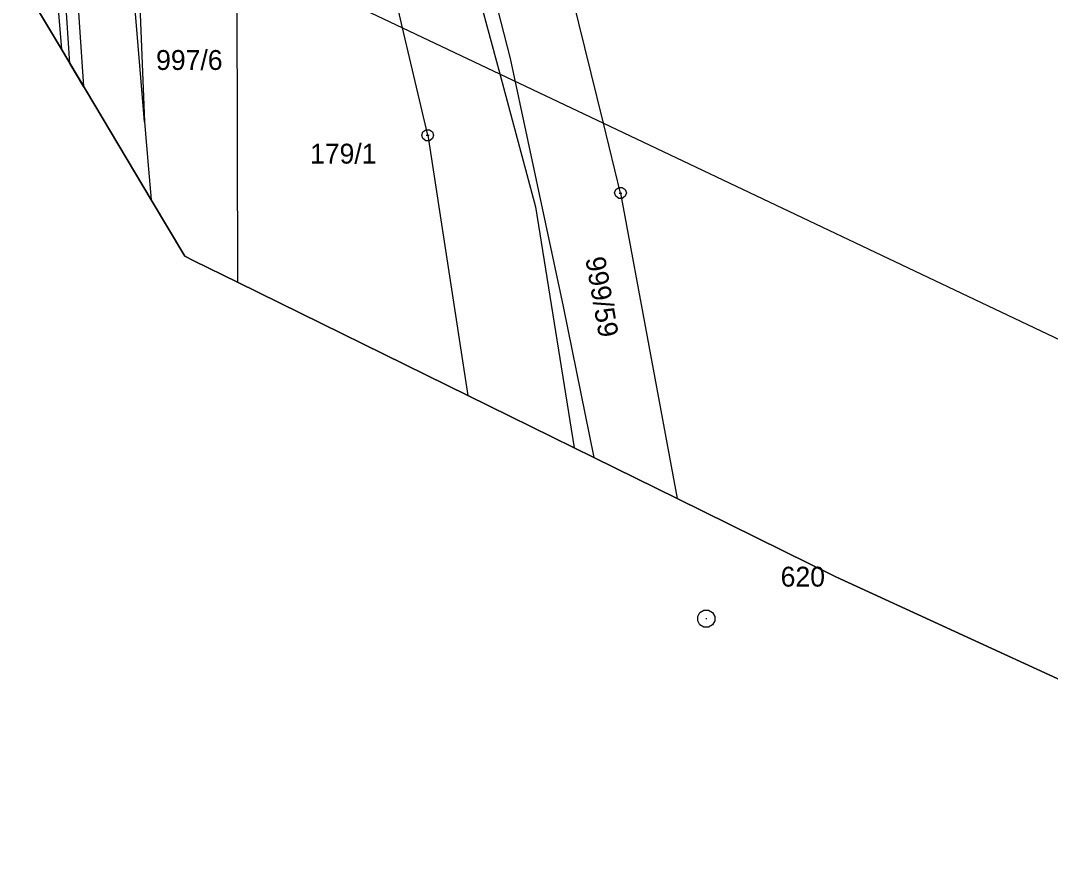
# Model space of a CAD drawing. Extents: x -755359 to -754474, y -1162585 to -1161655.
# Drawn here: x -755133.8 to -755045.7, y -1162567.4 to -1162495.1 of the extents above; entities that cross this region are included whole.
import ezdxf

# ---------------------------------------------------------------- set-up
doc = ezdxf.new("R2010")
doc.units = 0
for name, color, linetype in [('Vrstva 1', 7, 'Continuous'), ('Vrstva 11', 7, 'Continuous'), ('Vrstva 13', 7, 'Continuous'), ('Vrstva 2', 7, 'Continuous'), ('Vrstva 4', 7, 'Continuous'), ('Vrstva 6', 7, 'Continuous'), ('Vrstva 8', 7, 'Continuous')]:
    doc.layers.add(name, color=color, linetype=linetype)

msp = doc.modelspace()

# ---------------------------------------------------------------- linework, layer by layer
at = {"layer": 'Vrstva 1'}
for p, q in [((-755101.11, -1162495.7), (-755105.74, -1162475.9)), ((-755083.94, -1162503.85), (-755090.44, -1162477.46)), ((-755123.93, -1162484.86), (-755123.19, -1162503.76)), ((-755115.28, -1162488.97), (-755101.11, -1162495.7)), ((-755115.28, -1162488.97), (-755115.23, -1162517.45)), ((-755133.78, -1162491.69), (-755130.29, -1162497.54)), ((-755101.11, -1162495.7), (-755083.94, -1162503.85)), ((-755098.96, -1162504.9), (-755101.11, -1162495.7)), ((-755130.29, -1162497.54), (-755122.61, -1162510.43)), ((-755123.19, -1162503.76), (-755122.83, -1162507.8)), ((-755083.94, -1162503.85), (-754997.93, -1162544.71)), ((-755082.47, -1162509.84), (-755083.94, -1162503.85)), ((-755098.96, -1162504.9), (-755095.54, -1162527.15)), ((-755122.83, -1162507.8), (-755122.61, -1162510.43)), ((-755082.47, -1162509.84), (-755077.64, -1162535.97)), ((-755122.61, -1162510.43), (-755119.74, -1162515.24)), ((-755119.74, -1162515.24), (-755118.95, -1162515.63)), ((-755118.95, -1162515.63), (-755115.23, -1162517.45)), ((-755115.23, -1162517.45), (-755095.54, -1162527.15)), ((-755095.54, -1162527.15), (-755084.75, -1162532.46)), ((-755084.75, -1162532.46), (-755077.64, -1162535.97)), ((-755077.64, -1162535.97), (-755064.06, -1162542.65)), ((-755064.06, -1162542.65), (-755010.16, -1162567.43))]:
    msp.add_line(p, q, dxfattribs=at)
at = {"layer": 'Vrstva 11'}
for p, q in [((-755100.87, -1162469.57), (-755092.8, -1162499.65)), ((-755130.29, -1162497.54), (-755133.78, -1162491.69)), ((-755122.61, -1162510.43), (-755130.29, -1162497.54)), ((-755092.8, -1162499.65), (-755089.74, -1162511.02)), ((-755119.74, -1162515.24), (-755122.61, -1162510.43)), ((-755089.74, -1162511.02), (-755086.44, -1162531.63)), ((-755118.95, -1162515.63), (-755119.74, -1162515.24)), ((-755115.23, -1162517.45), (-755118.95, -1162515.63)), ((-755095.54, -1162527.15), (-755115.23, -1162517.45)), ((-755086.44, -1162531.63), (-755095.54, -1162527.15)), ((-755084.75, -1162532.46), (-755086.44, -1162531.63)), ((-755077.64, -1162535.97), (-755084.75, -1162532.46)), ((-755064.06, -1162542.65), (-755077.64, -1162535.97)), ((-755010.16, -1162567.43), (-755064.06, -1162542.65))]:
    msp.add_line(p, q, dxfattribs=at)
at = {"layer": 'Vrstva 13'}
for p, q in [((-755129.57, -1162498.75), (-755130.4, -1162485.92)), ((-755129.4, -1162485.84), (-755128.4, -1162500.72)), ((-755128.4, -1162500.72), (-755129.57, -1162498.75))]:
    msp.add_line(p, q, dxfattribs=at)
at = {"layer": 'Vrstva 4'}
for p, q in [((-755123.19, -1162503.76), (-755125.67, -1162473.35)), ((-755131.67, -1162480.93), (-755130.29, -1162497.54))]:
    msp.add_line(p, q, dxfattribs=at)
at = {"layer": 'Vrstva 6'}
for p, q in [((-755097.36, -1162476.75), (-755091.92, -1162498.32)), ((-755091.92, -1162498.32), (-755087.37, -1162519.53)), ((-755087.37, -1162519.53), (-755084.75, -1162532.46))]:
    msp.add_line(p, q, dxfattribs=at)
at = {"layer": 'Vrstva 8'}
for p, q in [((-755099.08, -1162504.9), (-755098.84, -1162504.9)), ((-755082.59, -1162509.84), (-755082.35, -1162509.84)), ((-755075.19, -1162546.24), (-755075.09, -1162546.24))]:
    msp.add_line(p, q, dxfattribs=at)
for points in [[(-755098.81, -1162504.42), (-755098.56, -1162504.6), (-755098.46, -1162504.89), (-755098.56, -1162505.18), (-755098.81, -1162505.36), (-755099.12, -1162505.36), (-755099.37, -1162505.18), (-755099.47, -1162504.89), (-755099.37, -1162504.6), (-755099.12, -1162504.42)], [(-755082.32, -1162509.36), (-755082.07, -1162509.54), (-755081.97, -1162509.83), (-755082.07, -1162510.12), (-755082.32, -1162510.3), (-755082.63, -1162510.3), (-755082.88, -1162510.12), (-755082.98, -1162509.83), (-755082.88, -1162509.54), (-755082.63, -1162509.36)], [(-755074.95, -1162545.52), (-755074.61, -1162545.71), (-755074.42, -1162546.05), (-755074.42, -1162546.44), (-755074.61, -1162546.78), (-755074.95, -1162546.97), (-755075.34, -1162546.97), (-755075.68, -1162546.78), (-755075.87, -1162546.44), (-755075.87, -1162546.05), (-755075.68, -1162545.71), (-755075.34, -1162545.52)]]:
    msp.add_lwpolyline(points, close=True, dxfattribs=at)

# ---------------------------------------------------------------- texts
at = {"layer": 'Vrstva 2'}
for s, p in [('997/6', (-755122.193, -1162499.31)), ('179/1', (-755109.027, -1162507.32))]:
    msp.add_text(s, height=1.7, dxfattribs=at).set_placement(p)
msp.add_text('999/59', height=1.7, rotation=279.88988, dxfattribs=at).set_placement((-755085.489, -1162515.434))
at = {"layer": 'Vrstva 8'}
msp.add_text('620', height=1.7, dxfattribs=at).set_placement((-755068.778, -1162543.5))

doc.saveas('drawing.dxf')
